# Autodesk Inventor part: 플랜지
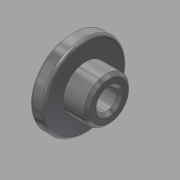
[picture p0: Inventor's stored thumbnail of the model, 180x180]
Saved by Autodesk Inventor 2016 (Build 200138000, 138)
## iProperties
Created: 2018-01
Part Number: 플랜지
Material: 스테인리스강
Document SubType Name: Modeling
Designer: mduedu
Density: 8.08 g/cm^3
Appearance: 반광택
Mass: 3.95967 g
Surface Area: 5.35087 cm^2
Volume: 0.490059 cm^3
Author: mduedu
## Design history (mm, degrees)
sketch "스케치1"
  geometry: L1 (0, 0)-(0, 7); L2 (0, 7)-(2.5, 7); L3 (2.5, 7)-(2.5, 3.75); L4 (2.5, 3.75)-(6.5, 3.75); L5 (6.5, 3.75)-(6.5, 0); L6 (6.5, 0)-(0, 0)
  constraints: 12 end point, 4 parallel, 1 perpendicular, 1 vertical
  dimensions: "d0" = 14 diameter of L2 L6; "d2" = 7.5 diameter of L4 L6; "d3" = 2.5 distance of L1.end L2.end; "d4" = 6.5 distance between parallel lines of L5 L1
revolve "회전1" sketch "스케치1" stored, may be unused: angle "d5" = 90 deg
hole "구멍1" diameter "d8" = 3.5; stored, may be unused: countersink angle "d12" = 90 deg, drill point angle "d14" = 118 deg; dims "d9" = 6, "d10" = 4, "d11" = 2, "d13" = 8, "d19" = 10, "d20" = 10
fillet "모깎기1" dims "d15" = 0.5
chamfer "모따기1" distance "d16" = 0.5; stored, may be unused: second distance "d17" = 2, angle "d18" = 45 deg
chamfer "모따기2" distance "d21" = 0.5; stored, may be unused: second distance "d22" = 2, angle "d23" = 45 deg
node "솔리드1"
